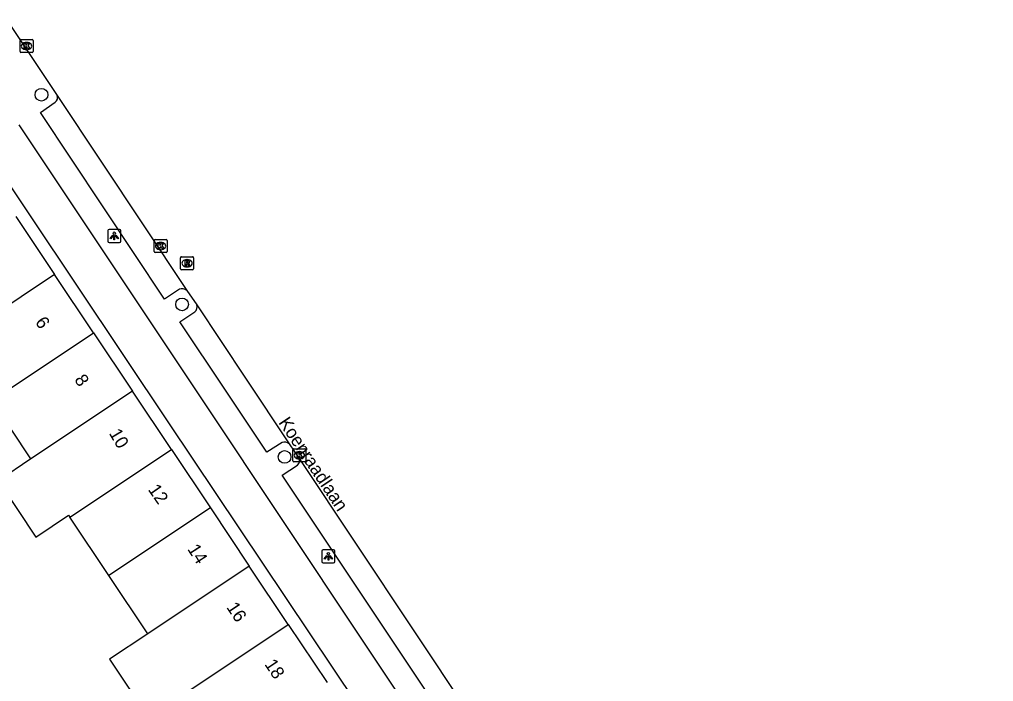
# Model space of a CAD drawing. Extents: x 158352 to 159489, y 383828 to 384597.
# Drawn here: x 158885.4 to 158960.3, y 384412.1 to 384463.1 of the extents above; entities that cross this region are included whole.
import ezdxf

# ---------------------------------------------------------------- set-up
doc = ezdxf.new("R2010")
doc.units = 0
for name, color, linetype in [('IMGEO_Boom', 7, 'Continuous'), ('IMGEO_Erf', 7, 'Continuous'), ('IMGEO_Kolk', 7, 'Continuous'), ('IMGEO_Lichtpunt', 7, 'Continuous'), ('IMGEO_Openbare_ruimte_label', 7, 'Continuous'), ('IMGEO_Pand', 7, 'Continuous'), ('IMGEO_Pand_nummerreeks', 7, 'Continuous'), ('IMGEO_Rijbaan_lokaal_gesloten', 7, 'Continuous'), ('IMGEO_Rioolput', 7, 'Continuous'), ('IMGEO_Voetpad_open', 7, 'Continuous')]:
    doc.layers.add(name, color=color, linetype=linetype)

msp = doc.modelspace()

# ---------------------------------------------------------------- linework, layer by layer
at = {"layer": 'IMGEO_Boom'}
for centre in [(158887.081, 384457.306), (158897.897, 384441.16), (158905.784, 384429.413)]:
    msp.add_circle(centre, 0.489, dxfattribs=at)
at = {"layer": 'IMGEO_Erf'}
msp.add_lwpolyline([(158958.047, 384340.708), (158896.943, 384431.973), (158882.708, 384453.235)], dxfattribs=at)
at = {"layer": 'IMGEO_Kolk'}
for p, q in [((158885.429, 384460.625), (158885.429, 384461.477)), ((158885.504, 384461.551), (158886.356, 384461.551)), ((158885.917, 384461.331), (158885.942, 384461.331)), ((158886.43, 384461.477), (158886.43, 384460.625)), ((158885.94, 384460.771), (158885.915, 384460.771)), ((158886.356, 384460.551), (158885.504, 384460.551)), ((158895.745, 384445.227), (158895.745, 384446.079)), ((158895.82, 384446.153), (158896.672, 384446.153)), ((158896.233, 384445.933), (158896.258, 384445.933)), ((158896.746, 384446.079), (158896.746, 384445.227)), ((158896.672, 384445.153), (158895.82, 384445.153)), ((158896.256, 384445.373), (158896.231, 384445.373)), ((158906.429, 384429.119), (158906.429, 384429.971)), ((158906.504, 384430.045), (158907.356, 384430.045)), ((158907.43, 384429.971), (158907.43, 384429.119)), ((158906.94, 384429.265), (158906.915, 384429.265)), ((158906.917, 384429.825), (158906.942, 384429.825)), ((158907.356, 384429.045), (158906.504, 384429.045))]:
    msp.add_line(p, q, dxfattribs=at)
for points in [[(158885.429, 384460.625), (158885.429, 384461.477)], [(158885.504, 384461.551), (158886.356, 384461.551)], [(158886.43, 384461.477), (158886.43, 384460.625)], [(158885.75, 384461.251), (158885.873, 384461.251), (158885.873, 384461.1), (158886.003, 384461.251), (158886.167, 384461.251), (158886.021, 384461.1), (158886.174, 384460.851), (158886.022, 384460.851), (158885.937, 384461.015), (158885.873, 384460.948), (158885.873, 384460.851), (158885.75, 384460.851), (158885.75, 384461.251)], [(158886.356, 384460.551), (158885.504, 384460.551)], [(158895.745, 384445.227), (158895.745, 384446.079)], [(158895.82, 384446.153), (158896.672, 384446.153)], [(158896.066, 384445.853), (158896.189, 384445.853), (158896.189, 384445.702), (158896.319, 384445.853), (158896.483, 384445.853), (158896.337, 384445.702), (158896.49, 384445.453), (158896.338, 384445.453), (158896.253, 384445.617), (158896.189, 384445.55), (158896.189, 384445.453), (158896.066, 384445.453), (158896.066, 384445.853)], [(158896.746, 384446.079), (158896.746, 384445.227)], [(158896.672, 384445.153), (158895.82, 384445.153)], [(158906.429, 384429.119), (158906.429, 384429.971)], [(158906.504, 384430.045), (158907.356, 384430.045)], [(158907.43, 384429.971), (158907.43, 384429.119)], [(158906.75, 384429.745), (158906.873, 384429.745), (158906.873, 384429.594), (158907.003, 384429.745), (158907.167, 384429.745), (158907.021, 384429.594), (158907.174, 384429.345), (158907.022, 384429.345), (158906.937, 384429.509), (158906.873, 384429.442), (158906.873, 384429.345), (158906.75, 384429.345), (158906.75, 384429.745)], [(158907.356, 384429.045), (158906.504, 384429.045)]]:
    msp.add_lwpolyline(points, dxfattribs=at)
for centre, start, end in [((158885.506, 384461.475), 91.55205, 178.44795), ((158885.506, 384461.475), 91.55205, 178.44795), ((158886.354, 384461.475), 1.55205, 88.44795), ((158886.354, 384461.475), 1.55205, 88.44795), ((158885.506, 384460.627), 181.55205, 268.44795), ((158885.506, 384460.627), 181.55205, 268.44795), ((158886.354, 384460.627), 271.55205, 358.44795), ((158886.354, 384460.627), 271.55205, 358.44795), ((158895.822, 384446.077), 91.55205, 178.44795), ((158895.822, 384446.077), 91.55205, 178.44795), ((158896.67, 384446.077), 1.55205, 88.44795), ((158896.67, 384446.077), 1.55205, 88.44795), ((158895.822, 384445.229), 181.55205, 268.44795), ((158895.822, 384445.229), 181.55205, 268.44795), ((158896.67, 384445.229), 271.55205, 358.44795), ((158896.67, 384445.229), 271.55205, 358.44795), ((158906.506, 384429.969), 91.55205, 178.44795), ((158906.506, 384429.969), 91.55205, 178.44795), ((158907.354, 384429.969), 1.55205, 88.44795), ((158907.354, 384429.969), 1.55205, 88.44795), ((158906.506, 384429.121), 181.55205, 268.44795), ((158906.506, 384429.121), 181.55205, 268.44795), ((158907.354, 384429.121), 271.55205, 358.44795), ((158907.354, 384429.121), 271.55205, 358.44795)]:
    msp.add_arc(centre, 0.0765, start, end, dxfattribs=at)
for centre, major_axis, ratio, start_param, end_param in [((158885.916, 384461.051), (-0.387, 0.002), 0.722429, 4.712389, 7.853982), ((158885.941, 384461.051), (-0.39, 0.002), 0.717154, 1.570796, 4.712389), ((158896.232, 384445.653), (-0.387, 0.002), 0.722429, 4.712389, 7.853982), ((158896.257, 384445.653), (-0.39, 0.002), 0.717154, 1.570796, 4.712389), ((158906.916, 384429.545), (-0.387, 0.002), 0.722429, 4.712389, 7.853982), ((158906.941, 384429.545), (-0.39, 0.002), 0.717154, 1.570796, 4.712389)]:
    msp.add_ellipse(centre, major_axis=major_axis, ratio=ratio, start_param=start_param, end_param=end_param, dxfattribs=at)
at = {"layer": 'IMGEO_Lichtpunt'}
for p, q in [((158892.185, 384446.839), (158892.185, 384446.032)), ((158892.185, 384446.839), (158892.185, 384446.032)), ((158893.087, 384446.934), (158892.279, 384446.934)), ((158893.087, 384446.934), (158892.279, 384446.934)), ((158893.181, 384446.032), (158893.181, 384446.839)), ((158893.181, 384446.032), (158893.181, 384446.839)), ((158892.279, 384445.938), (158893.087, 384445.938)), ((158892.279, 384445.938), (158893.087, 384445.938)), ((158908.658, 384422.166), (158908.658, 384421.359)), ((158908.658, 384422.166), (158908.658, 384421.359)), ((158909.56, 384422.261), (158908.752, 384422.261)), ((158909.56, 384422.261), (158908.752, 384422.261)), ((158909.654, 384421.359), (158909.654, 384422.166)), ((158909.654, 384421.359), (158909.654, 384422.166)), ((158908.752, 384421.265), (158909.56, 384421.265)), ((158908.752, 384421.265), (158909.56, 384421.265))]:
    msp.add_line(p, q, dxfattribs=at)
for points in [[(158892.559, 384446.503), (158892.598, 384446.475), (158892.41, 384446.213), (158892.372, 384446.24), (158892.559, 384446.503)], [(158892.661, 384446.455), (158892.708, 384446.455), (158892.708, 384446.133), (158892.661, 384446.133), (158892.661, 384446.455)], [(158892.771, 384446.475), (158892.809, 384446.502), (158892.996, 384446.24), (158892.957, 384446.212), (158892.771, 384446.475)], [(158909.032, 384421.83), (158909.071, 384421.802), (158908.883, 384421.54), (158908.845, 384421.567), (158909.032, 384421.83)], [(158909.134, 384421.782), (158909.181, 384421.782), (158909.181, 384421.46), (158909.134, 384421.46), (158909.134, 384421.782)], [(158909.244, 384421.802), (158909.282, 384421.829), (158909.469, 384421.567), (158909.43, 384421.539), (158909.244, 384421.802)]]:
    msp.add_lwpolyline(points, dxfattribs=at)
for centre in [(158892.684, 384446.637), (158909.157, 384421.964)]:
    msp.add_circle(centre, 0.0994, dxfattribs=at)
for centre, start, end in [((158892.279, 384446.839), 90, 180), ((158892.279, 384446.839), 90, 180), ((158893.087, 384446.839), 0, 90), ((158893.087, 384446.839), 0, 90), ((158892.279, 384446.032), 180, 270), ((158892.279, 384446.032), 180, 270), ((158893.087, 384446.032), 270, 0), ((158893.087, 384446.032), 270, 360), ((158908.752, 384422.166), 90, 180), ((158908.752, 384422.166), 90, 180), ((158909.56, 384422.166), 0, 90), ((158909.56, 384422.166), 0, 90), ((158908.752, 384421.359), 180, 270), ((158908.752, 384421.359), 180, 270), ((158909.56, 384421.359), 270, 0), ((158909.56, 384421.359), 270, 360)]:
    msp.add_arc(centre, 0.0946, start, end, dxfattribs=at)
at = {"layer": 'IMGEO_Pand'}
for points in [[(158885.098, 384447.937), (158888.089, 384443.457)], [(158888.089, 384443.457), (158880.272, 384438.249)], [(158891.089, 384438.962), (158888.089, 384443.457)], [(158883.272, 384433.755), (158891.089, 384438.962)], [(158891.089, 384438.962), (158894.09, 384434.468)], [(158894.09, 384434.468), (158886.273, 384429.26)], [(158897.081, 384429.988), (158894.09, 384434.468)], [(158886.273, 384429.26), (158883.272, 384433.755)], [(158889.263, 384424.78), (158897.081, 384429.988)], [(158897.081, 384429.988), (158900.082, 384425.492)], [(158886.273, 384429.26), (158883.741, 384427.573), (158886.635, 384423.238), (158889.165, 384424.926), (158889.263, 384424.78)], [(158900.082, 384425.492), (158892.264, 384420.284)], [(158900.082, 384425.492), (158903.072, 384421.013)], [(158892.264, 384420.284), (158889.263, 384424.78)], [(158903.072, 384421.013), (158895.254, 384415.804)], [(158906.071, 384416.517), (158903.072, 384421.013)], [(158895.254, 384415.804), (158892.264, 384420.284)], [(158898.254, 384411.31), (158906.071, 384416.517)], [(158906.071, 384416.517), (158909.059, 384412.037)], [(158895.254, 384415.804), (158892.313, 384413.844), (158895.312, 384409.35), (158898.254, 384411.31)]]:
    msp.add_lwpolyline(points, dxfattribs=at)
at = {"layer": 'IMGEO_Rijbaan_lokaal_gesloten'}
for points in [[(158884.4, 384463.1), (158888.28, 384457.252)], [(158888.28, 384457.252), (158898.259, 384442.243)], [(158898.259, 384442.243), (158899.028, 384441.124)], [(158899.028, 384441.124), (158902.775, 384435.489), (158906.139, 384430.429)], [(158906.139, 384430.429), (158906.908, 384429.304)], [(158906.908, 384429.304), (158920.007, 384409.58)]]:
    msp.add_lwpolyline(points, dxfattribs=at)
at = {"layer": 'IMGEO_Rioolput'}
for p, q in [((158897.787, 384443.907), (158897.787, 384444.759)), ((158897.862, 384444.833), (158898.714, 384444.833)), ((158898.275, 384444.613), (158898.3, 384444.613)), ((158898.788, 384444.759), (158898.788, 384443.907)), ((158898.714, 384443.833), (158897.862, 384443.833)), ((158898.298, 384444.053), (158898.273, 384444.053))]:
    msp.add_line(p, q, dxfattribs=at)
for points in [[(158897.787, 384443.907), (158897.787, 384444.759)], [(158897.862, 384444.833), (158898.714, 384444.833)], [(158898.376, 384444.531), (158898.124, 384444.533), (158898.124, 384444.133)], [(158898.124, 384444.133), (158898.248, 384444.133), (158898.248, 384444.295), (158898.259, 384444.295)], [(158898.302, 384444.452), (158898.248, 384444.452), (158898.248, 384444.371)], [(158898.248, 384444.371), (158898.3, 384444.371)], [(158898.306, 384444.266), (158898.377, 384444.133), (158898.517, 384444.133), (158898.452, 384444.259)], [(158898.788, 384444.759), (158898.788, 384443.907)], [(158898.714, 384443.833), (158897.862, 384443.833)]]:
    msp.add_lwpolyline(points, dxfattribs=at)
for centre, radius, start, end in [((158897.864, 384444.757), 0.0765, 91.55205, 178.44795), ((158897.864, 384444.757), 0.0765, 91.55205, 178.44795), ((158898.258, 384444.242), 0.0533, 26.02933, 88.69889), ((158898.284, 384444.56), 0.19, 274.7715, 282.96867), ((158898.308, 384444.356), 0.0964, 77.00612, 93.18647), ((158898.322, 384444.413), 0.0378, 276.66336, 79.67722), ((158898.375, 384444.421), 0.109, 350.36119, 89.41601), ((158898.373, 384444.421), 0.112, 277.58423, 350.98172), ((158898.357, 384444.206), 0.108, 29.51342, 73.79051), ((158898.712, 384444.757), 0.0765, 1.55205, 88.44795), ((158898.712, 384444.757), 0.0765, 1.55205, 88.44795), ((158897.864, 384443.909), 0.0765, 181.55205, 268.44795), ((158897.864, 384443.909), 0.0765, 181.55205, 268.44795), ((158898.712, 384443.909), 0.0765, 271.55205, 358.44795), ((158898.712, 384443.909), 0.0765, 271.55205, 358.44795)]:
    msp.add_arc(centre, radius, start, end, dxfattribs=at)
for centre, major_axis, ratio, start_param, end_param in [((158898.274, 384444.333), (-0.387, 0.002), 0.722429, 4.712389, 7.853982), ((158898.299, 384444.333), (-0.39, 0.002), 0.717154, 1.570796, 4.712389)]:
    msp.add_ellipse(centre, major_axis=major_axis, ratio=ratio, start_param=start_param, end_param=end_param, dxfattribs=at)
at = {"layer": 'IMGEO_Voetpad_open'}
for points in [[(158897.695, 384442.327), (158896.557, 384441.558), (158886.996, 384455.934), (158888.14, 384456.722)], [(158885.345, 384454.99), (158899.598, 384433.573), (158960.345, 384342.297)], [(158905.595, 384430.523), (158904.435, 384429.772), (158901.234, 384434.56), (158897.72, 384439.815), (158898.875, 384440.591)], [(158919.442, 384409.685), (158918.329, 384408.917), (158905.59, 384428.007), (158906.78, 384428.795)]]:
    msp.add_lwpolyline(points, dxfattribs=at)
for centre, radius, start, end in [((158887.878, 384457.075), 0.439, 306.58056, 23.82592), ((158897.904, 384441.792), 0.574, 51.75131, 111.3064), ((158898.584, 384440.963), 0.472, 308.0531, 19.91418), ((158905.783, 384429.99), 0.565, 50.95527, 109.43759), ((158906.525, 384429.13), 0.421, 307.32304, 24.44562)]:
    msp.add_arc(centre, radius, start, end, dxfattribs=at)

# ---------------------------------------------------------------- texts
at = {"layer": 'IMGEO_Openbare_ruimte_label'}
msp.add_text('Koenraadlaan', height=1, rotation=303.70596, dxfattribs=at).set_placement((158905.285, 384432.068))
at = {"layer": 'IMGEO_Pand_nummerreeks'}
for s, rotation, p in [('6', 304.52623, (158886.554, 384439.793)), ('8', 304.10594, (158889.571, 384435.357)), ('10', 300.59001, (158892.244, 384431.242)), ('12', 304.81587, (158895.24, 384426.901)), ('14', 302.69638, (158898.276, 384422.321)), ('16', 303.82722, (158901.278, 384417.834)), ('18', 303.68158, (158904.207, 384413.453))]:
    msp.add_text(s, height=1, rotation=rotation, dxfattribs=at).set_placement(p)

doc.saveas('drawing.dxf')
